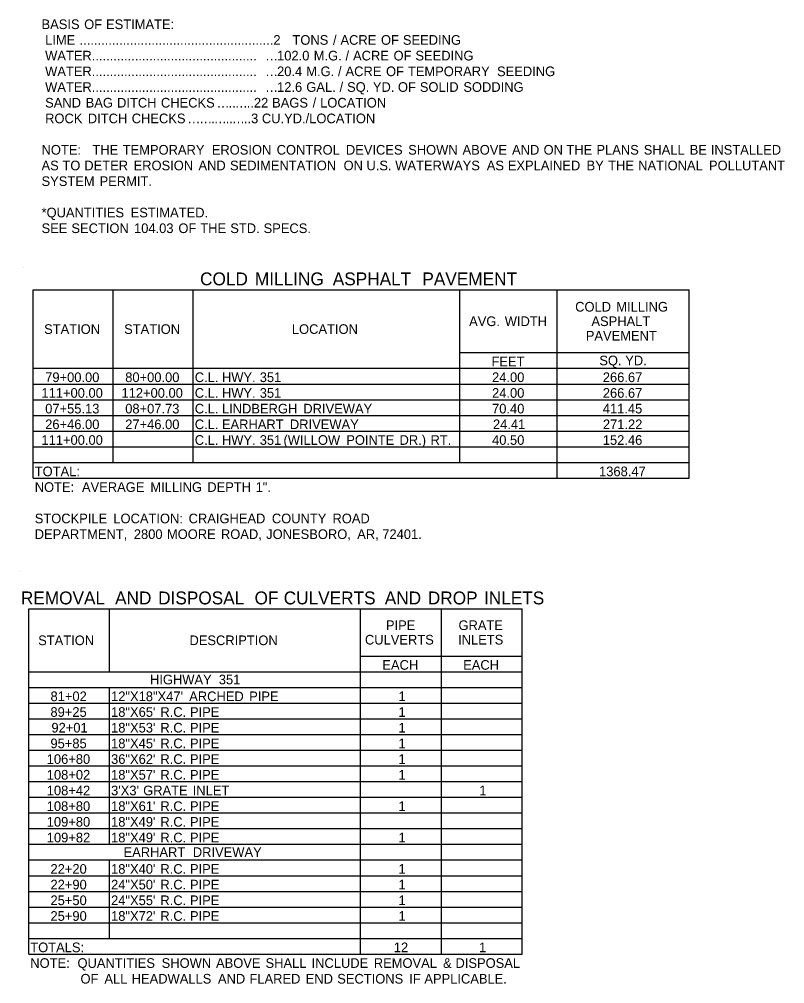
# Model space of a CAD drawing. Extents: x 1197542 to 1207068, y 230488 to 237324.
# Drawn here: x 1199831 to 1200307, y 231772 to 232371 of the extents above; entities that cross this region are included whole.
import ezdxf

# ---------------------------------------------------------------- set-up
doc = ezdxf.new("R2010")
doc.units = 0
doc.layers.add('Default', color=7, linetype='Continuous')

msp = doc.modelspace()

# ---------------------------------------------------------------- linework, layer by layer
at = {"layer": 'Default'}
for p, q in [((1199834.14, 232216.72), (1199834.14, 232216.72)), ((1199839.99, 232203.07), (1200247.54, 232203.07)), ((1199839.99, 232086.07), (1199839.99, 232203.07)), ((1199839.99, 232086.07), (1199839.99, 232203.07)), ((1199889.71, 232095.82), (1199889.71, 232203.07)), ((1199939.44, 232095.82), (1199939.44, 232203.07)), ((1200105.19, 232095.82), (1200105.19, 232203.07)), ((1200165.64, 232086.07), (1200165.64, 232203.07)), ((1200247.54, 232086.07), (1200247.54, 232203.07)), ((1200247.54, 232086.07), (1200247.54, 232203.07)), ((1200105.19, 232164.07), (1200247.54, 232164.07)), ((1200105.19, 232095.82), (1200105.19, 232164.07)), ((1199839.99, 232154.32), (1200247.54, 232154.32)), ((1199889.71, 232095.82), (1199889.71, 232154.32)), ((1199939.44, 232095.82), (1199939.44, 232154.32)), ((1200165.64, 232095.82), (1200165.64, 232154.32)), ((1199839.99, 232144.57), (1200247.54, 232144.57)), ((1199839.99, 232134.82), (1200247.54, 232134.82)), ((1199839.99, 232125.07), (1200247.54, 232125.07)), ((1199839.99, 232115.32), (1200247.54, 232115.32)), ((1199839.99, 232105.57), (1200247.54, 232105.57)), ((1199939.44, 232105.57), (1200105.19, 232105.57)), ((1200105.19, 232105.57), (1200247.54, 232105.57)), ((1199839.99, 232095.82), (1199889.71, 232095.82)), ((1199839.99, 232095.82), (1200247.54, 232095.82)), ((1199889.71, 232095.82), (1199939.44, 232095.82)), ((1199939.44, 232095.82), (1200105.19, 232095.82)), ((1200165.64, 232095.82), (1200247.54, 232095.82)), ((1199839.99, 232086.07), (1200247.54, 232086.07)), ((1199831.36, 232028.21), (1199831.36, 232028.21)), ((1199837.21, 232004.81), (1200143.85, 232004.81)), ((1199837.21, 231790.31), (1199837.21, 232004.81)), ((1199837.21, 231790.31), (1199837.21, 232004.81)), ((1199887.42, 231965.81), (1199887.42, 232004.81)), ((1200043.42, 231790.31), (1200043.42, 232004.81)), ((1200093.64, 231790.31), (1200093.64, 232004.81)), ((1200143.85, 231790.31), (1200143.85, 232004.81)), ((1200043.42, 231975.56), (1200143.85, 231975.56)), ((1200093.64, 231878.06), (1200093.64, 231975.56)), ((1199837.21, 231965.81), (1200143.85, 231965.81)), ((1200093.64, 231965.81), (1200143.85, 231965.81)), ((1199837.21, 231956.06), (1200043.42, 231956.06)), ((1199887.42, 231878.06), (1199887.42, 231956.06)), ((1199887.42, 231858.56), (1199887.42, 231956.06)), ((1200043.42, 231956.06), (1200143.85, 231956.06)), ((1200043.42, 231858.56), (1200043.42, 231956.06)), ((1199837.21, 231946.31), (1200143.85, 231946.31)), ((1199837.21, 231936.56), (1200143.85, 231936.56)), ((1199837.21, 231926.81), (1200143.85, 231926.81)), ((1199837.21, 231917.06), (1200143.85, 231917.06)), ((1199837.21, 231907.31), (1200143.85, 231907.31)), ((1199837.21, 231897.56), (1200143.85, 231897.56)), ((1199837.21, 231887.81), (1200143.85, 231887.81)), ((1199837.21, 231878.06), (1200143.85, 231878.06)), ((1199887.42, 231878.06), (1200043.42, 231878.06)), ((1200043.42, 231878.06), (1200143.85, 231878.06)), ((1199837.21, 231868.31), (1200143.85, 231868.31)), ((1199887.42, 231868.31), (1200043.42, 231868.31)), ((1200043.42, 231868.31), (1200093.64, 231868.31)), ((1200093.64, 231868.31), (1200143.85, 231868.31)), ((1199837.21, 231858.56), (1200043.42, 231858.56)), ((1199887.42, 231858.56), (1200043.42, 231858.56)), ((1200043.42, 231858.56), (1200143.85, 231858.56)), ((1200093.64, 231858.56), (1200143.85, 231858.56)), ((1200093.64, 231790.31), (1200093.64, 231858.56)), ((1199837.21, 231848.81), (1200043.42, 231848.81)), ((1199887.42, 231800.06), (1199887.42, 231848.81)), ((1199887.42, 231800.06), (1199887.42, 231848.81)), ((1200043.42, 231848.81), (1200143.85, 231848.81)), ((1200043.42, 231790.31), (1200043.42, 231848.81)), ((1199837.21, 231839.06), (1200143.85, 231839.06)), ((1199837.21, 231829.31), (1200143.85, 231829.31)), ((1199837.21, 231819.56), (1200143.85, 231819.56)), ((1199837.21, 231809.81), (1200143.85, 231809.81)), ((1199837.21, 231800.06), (1200143.85, 231800.06)), ((1199837.21, 231790.31), (1200143.85, 231790.31))]:
    msp.add_line(p, q, dxfattribs=at)

# ---------------------------------------------------------------- texts
for s, height, p in [('BASIS', 6, (1199845.19, 232365.11)), (' OF', 6, (1199869.45, 232365.11)), (' ESTIMATE:', 6, (1199883.04, 232365.11)), (' LIME', 6, (1199845.19, 232355.36)), (' ......................................................2', 6, (1199866.63, 232355.36)), (' TONS', 6, (1199998.88, 232355.36)), (' /', 6, (1200024.06, 232355.36)), (' ACRE', 6, (1200028.72, 232355.36)), (' OF', 6, (1200053.89, 232355.36)), (' SEEDING', 6, (1200067.48, 232355.36)), (' WATER..............................................', 6, (1199845.19, 232345.61)), ('102.0', 6, (1199991.54, 232345.61)), (' M.G.', 6, (1200012.1, 232345.61)), (' /', 6, (1200031.86, 232345.61)), (' ACRE', 6, (1200036.52, 232345.61)), (' OF', 6, (1200061.69, 232345.61)), (' SEEDING', 6, (1200075.28, 232345.61)), ('…', 6, (1199984.14, 232345.61)), (' WATER..............................................', 6, (1199845.19, 232335.86)), ('20.4', 6, (1199991.54, 232335.86)), (' M.G.', 6, (1200007.44, 232335.86)), (' /', 6, (1200027.19, 232335.86)), (' ACRE', 6, (1200031.85, 232335.86)), (' OF', 6, (1200057.03, 232335.86)), (' TEMPORARY', 6, (1200070.62, 232335.86)), (' SEEDING', 6, (1200125.99, 232335.86)), (' WATER..............................................', 6, (1199845.19, 232326.11)), ('…', 6, (1199984.14, 232335.86)), ('12.6', 6, (1199991.54, 232326.11)), (' GAL.', 6, (1200007.47, 232326.11)), (' /', 6, (1200028.16, 232326.11)), (' SQ.', 6, (1200032.82, 232326.11)), (' YD.', 6, (1200048.86, 232326.11)), (' OF', 6, (1200064.43, 232326.11)), (' SOLID', 6, (1200078.02, 232326.11)), (' SODDING', 6, (1200105.06, 232326.11)), ('…', 6, (1199984.14, 232326.11)), (' SAND', 6, (1199845.19, 232316.36)), (' BAG', 6, (1199870.37, 232316.36)), (' DITCH', 6, (1199889.88, 232316.36)), (' CHECKS', 6, (1199917.14, 232316.36)), ('..22', 6, (1199972.7, 232316.36)), (' BAGS', 6, (1199986.23, 232316.36)), (' /', 6, (1200011.42, 232316.36)), (' LOCATION', 6, (1200016.08, 232316.36)), ('…', 6, (1199953.97, 232316.36)), ('..', 6, (1199961.37, 232316.36)), ('…', 6, (1199965.3, 232316.36)), (' ROCK', 6, (1199845.19, 232306.61)), (' DITCH', 6, (1199871.72, 232306.61)), (' CHECKS', 6, (1199898.99, 232306.61)), ('..3', 6, (1199970.94, 232306.61)), (' CU.YD./LOCATION', 6, (1199979.88, 232306.61)), ('…', 6, (1199935.82, 232306.61)), ('…', 6, (1199943.22, 232306.61)), ('.', 6, (1199950.62, 232306.61)), ('…', 6, (1199952.22, 232306.61)), ('..', 6, (1199959.62, 232306.61)), ('…', 6, (1199963.54, 232306.61)), ('NOTE:', 6, (1199845.19, 232287.11)), ('   THE', 6, (1199870.08, 232287.11)), (' TEMPORARY', 6, (1199893.38, 232287.11)), (' EROSION', 6, (1199948.75, 232287.11)), (' CONTROL', 6, (1199989.06, 232287.11)), (' DEVICES', 6, (1200032.08, 232287.11)), (' SHOWN', 6, (1200070.78, 232287.11)), (' ABOVE', 6, (1200104.56, 232287.11)), (' AND', 6, (1200135.33, 232287.11)), (' ON', 6, (1200154.91, 232287.11)), (' THE', 6, (1200169.13, 232287.11)), (' PLANS', 6, (1200187.78, 232287.11)), (' SHALL', 6, (1200217.16, 232287.11)), (' BE', 6, (1200245.75, 232287.11)), (' INSTALLED', 6, (1200258.82, 232287.11)), ('AS', 6, (1199845.19, 232277.36)), (' TO', 6, (1199855.94, 232277.36)), (' DETER', 6, (1199869.53, 232277.36)), (' EROSION', 6, (1199900.16, 232277.36)), (' AND', 6, (1199940.47, 232277.36)), (' SEDIMENTATION', 6, (1199960.06, 232277.36)), (' ON', 6, (1200030.64, 232277.36)), (' U.S.', 6, (1200044.86, 232277.36)), (' WATERWAYS', 6, (1200062.75, 232277.36)), (' AS', 6, (1200119.61, 232277.36)), (' EXPLAINED', 6, (1200132.68, 232277.36)), (' BY', 6, (1200181.63, 232277.36)), (' THE', 6, (1200195.07, 232277.36)), (' NATIONAL', 6, (1200213.72, 232277.36)), (' POLLUTANT', 6, (1200257.68, 232277.36)), ('SYSTEM', 6, (1199845.19, 232267.61)), (' PERMIT.', 6, (1199879.04, 232267.61)), ('*QUANTITIES', 6, (1199845.19, 232248.11)), (' ESTIMATED.', 6, (1199898.32, 232248.11)), ('SEE', 6, (1199845.19, 232238.36)), (' SECTION', 6, (1199861.52, 232238.36)), (' 104.03', 6, (1199900.43, 232238.36)), (' OF', 6, (1199928.01, 232238.36)), (' THE', 6, (1199941.59, 232238.36)), (' STD.', 6, (1199960.24, 232238.36)), (' SPECS.', 6, (1199980.94, 232238.36)), ('COLD', 8, (1199943.69, 232205.89)), (' MILLING', 8, (1199974.81, 232205.89)), (' ASPHALT', 8, (1200023.18, 232205.89)), (' PAVEMENT', 8, (1200078.85, 232205.89)), ('COLD', 6, (1200176.78, 232189.57)), (' MILLING', 6, (1200200.12, 232189.57)), ('AVG.', 6, (1200110.88, 232180.57)), (' WIDTH', 6, (1200130.8, 232180.57)), ('ASPHALT', 6, (1200186.88, 232180.57)), ('STATION', 6, (1199846.79, 232175.69)), ('STATION', 6, (1199896.51, 232175.69)), ('LOCATION', 6, (1200000.76, 232175.69)), ('PAVEMENT', 6, (1200183.38, 232171.57)), ('FEET', 6, (1200124.79, 232155.52)), ('SQ.', 6, (1200191.79, 232156.19)), (' YD.', 6, (1200205.66, 232156.19)), ('79+00.00', 6, (1199847.46, 232145.77)), ('80+00.00', 6, (1199897.19, 232145.77)), ('C.L.', 6, (1199940.41, 232145.77)), (' HWY.', 6, (1199955.05, 232145.77)), (' 351', 6, (1199978.54, 232145.77)), ('24.00', 6, (1200125.13, 232145.77)), ('266.67', 6, (1200193.96, 232145.77)), ('111+00.00', 6, (1199845.13, 232136.02)), ('112+00.00', 6, (1199894.86, 232136.02)), ('C.L.', 6, (1199940.41, 232136.02)), (' HWY.', 6, (1199955.05, 232136.02)), (' 351', 6, (1199978.54, 232136.02)), ('24.00', 6, (1200125.13, 232136.02)), ('266.67', 6, (1200193.96, 232136.02)), ('07+55.13', 6, (1199847.45, 232126.27)), ('08+07.73', 6, (1199897.18, 232126.27)), ('C.L.', 6, (1199940.41, 232126.27)), (' LINDBERGH', 6, (1199955.05, 232126.27)), (' DRIVEWAY', 6, (1200005.62, 232126.27)), ('70.40', 6, (1200125.13, 232126.27)), ('411.45', 6, (1200193.94, 232126.27)), ('26+46.00', 6, (1199847.46, 232116.52)), ('27+46.00', 6, (1199897.19, 232116.52)), ('C.L.', 6, (1199940.41, 232116.52)), (' EARHART', 6, (1199955.05, 232116.52)), (' DRIVEWAY', 6, (1199997.28, 232116.52)), ('24.41', 6, (1200125.7, 232116.52)), ('271.22', 6, (1200194, 232116.52)), ('111+00.00', 6, (1199845.13, 232106.77)), ('C.L.', 6, (1199940.41, 232106.77)), (' HWY.', 6, (1199955.05, 232106.77)), (' 351', 6, (1199978.54, 232106.77)), (' (WILLOW', 6, (1199993.3, 232106.77)), (' POINTE', 6, (1200032.32, 232106.77)), (' DR.)', 6, (1200065.41, 232106.77)), (' RT.', 6, (1200084.66, 232106.77)), ('40.50', 6, (1200125.13, 232106.77)), ('152.46', 6, (1200193.96, 232106.77)), ('TOTAL:', 6, (1199840.96, 232087.27)), ('1368.47', 6, (1200191.63, 232087.27)), ('NOTE:', 6, (1199840.96, 232077.52)), ('  AVERAGE', 6, (1199865.85, 232077.52)), (' MILLING', 6, (1199910.6, 232077.52)), (' DEPTH', 6, (1199945.94, 232077.52)), (' 1".', 6, (1199976, 232077.52)), ('STOCKPILE', 6, (1199840.96, 232058.02)), (' LOCATION:', 6, (1199887.57, 232058.02)), (' CRAIGHEAD', 6, (1199934.35, 232058.02)), (' COUNTY', 6, (1199986.08, 232058.02)), (' ROAD', 6, (1200023.74, 232058.02)), ('DEPARTMENT,', 6, (1199840.96, 232048.27)), (' 2800', 6, (1199900.31, 232048.27)), (' MOORE', 6, (1199920.88, 232048.27)), (' ROAD,', 6, (1199954.43, 232048.27)), (' JONESBORO,', 6, (1199982.56, 232048.27)), (' AR,', 6, (1200039.12, 232048.27)), (' 72401.', 6, (1200054.68, 232048.27)), ('REMOVAL', 8, (1199832.34, 232007.64)), (' AND', 8, (1199887.9, 232007.64)), (' DISPOSAL', 8, (1199914.67, 232007.64)), (' OF', 8, (1199974.58, 232007.64)), (' CULVERTS', 8, (1199992.69, 232007.64)), (' AND', 8, (1200055.5, 232007.64)), (' DROP', 8, (1200082.26, 232007.64)), (' INLETS', 8, (1200117.15, 232007.64)), ('PIPE', 6, (1200059.19, 231991.69)), ('GRATE', 6, (1200104.28, 231991.69)), ('STATION', 6, (1199843.09, 231982.31)), ('DESCRIPTION', 6, (1199937.11, 231982.31)), ('CULVERTS', 6, (1200046.14, 231982.69)), ('INLETS', 6, (1200104.04, 231982.69)), ('EACH', 6, (1200056.97, 231967.01)), ('EACH', 6, (1200107.19, 231967.01)), ('HIGHWAY', 6, (1199912.58, 231957.94)), (' 351', 6, (1199953.11, 231957.94)), ('81+02', 6, (1199850.77, 231947.51)), ('12"X18"X47\'', 6, (1199888.4, 231947.51)), (' ARCHED', 6, (1199934.71, 231947.51)), (' PIPE', 6, (1199971.99, 231947.51)), ('1', 6, (1200066.97, 231947.51)), ('89+25', 6, (1199850.72, 231937.76)), ('18"X65\'', 6, (1199888.4, 231937.76)), (' R.C.', 6, (1199916.82, 231937.76)), (' PIPE', 6, (1199935.18, 231937.76)), ('1', 6, (1200066.97, 231937.76)), ('92+01', 6, (1199851.32, 231928.01)), ('18"X53\'', 6, (1199888.4, 231928.01)), (' R.C.', 6, (1199916.82, 231928.01)), (' PIPE', 6, (1199935.18, 231928.01)), ('1', 6, (1200066.97, 231928.01)), ('95+85', 6, (1199850.72, 231918.26)), ('18"X45\'', 6, (1199888.4, 231918.26)), (' R.C.', 6, (1199916.82, 231918.26)), (' PIPE', 6, (1199935.18, 231918.26)), ('1', 6, (1200066.97, 231918.26)), ('106+80', 6, (1199848.42, 231908.51)), ('36"X62\'', 6, (1199888.4, 231908.51)), (' R.C.', 6, (1199916.82, 231908.51)), (' PIPE', 6, (1199935.18, 231908.51)), ('1', 6, (1200066.97, 231908.51)), ('108+02', 6, (1199848.44, 231898.76)), ('18"X57\'', 6, (1199888.4, 231898.76)), (' R.C.', 6, (1199916.82, 231898.76)), (' PIPE', 6, (1199935.18, 231898.76)), ('1', 6, (1200066.97, 231898.76)), ('108+42', 6, (1199848.44, 231889.01)), ("3'X3'", 6, (1199888.4, 231889.01)), (' GRATE', 6, (1199906.12, 231889.01)), (' INLET', 6, (1199936.88, 231889.01)), ('1', 6, (1200117.18, 231889.01)), ('108+80', 6, (1199848.42, 231879.26)), ('18"X61\'', 6, (1199888.4, 231879.26)), (' R.C.', 6, (1199916.82, 231879.26)), (' PIPE', 6, (1199935.18, 231879.26)), ('1', 6, (1200066.97, 231879.26)), ('109+80', 6, (1199848.42, 231869.51)), ('18"X49\'', 6, (1199888.4, 231869.51)), (' R.C.', 6, (1199916.82, 231869.51)), (' PIPE', 6, (1199935.18, 231869.51)), ('109+82', 6, (1199848.44, 231859.76)), ('18"X49\'', 6, (1199888.4, 231859.76)), (' R.C.', 6, (1199916.82, 231859.76)), (' PIPE', 6, (1199935.18, 231859.76)), ('1', 6, (1200066.97, 231859.76)), ('EARHART', 6, (1199896.15, 231850.69)), (' DRIVEWAY', 6, (1199936.96, 231850.69)), ('22+20', 6, (1199850.75, 231840.26)), ('18"X40\'', 6, (1199888.4, 231840.26)), (' R.C.', 6, (1199916.82, 231840.26)), (' PIPE', 6, (1199935.18, 231840.26)), ('1', 6, (1200066.97, 231840.26)), ('22+90', 6, (1199850.75, 231830.51)), ('24"X50\'', 6, (1199888.4, 231830.51)), (' R.C.', 6, (1199916.82, 231830.51)), (' PIPE', 6, (1199935.18, 231830.51)), ('1', 6, (1200066.97, 231830.51)), ('25+50', 6, (1199850.75, 231820.76)), ('24"X55\'', 6, (1199888.4, 231820.76)), (' R.C.', 6, (1199916.82, 231820.76)), (' PIPE', 6, (1199935.18, 231820.76)), ('1', 6, (1200066.97, 231820.76)), ('25+90', 6, (1199850.75, 231811.01)), ('18"X72\'', 6, (1199888.4, 231811.01)), (' R.C.', 6, (1199916.82, 231811.01)), (' PIPE', 6, (1199935.18, 231811.01)), ('1', 6, (1200066.97, 231811.01)), ('TOTALS:', 6, (1199838.19, 231791.51)), ('12', 6, (1200064.08, 231791.51)), ('1', 6, (1200117.09, 231791.51)), ('NOTE:', 6, (1199838.19, 231781.76)), ('  QUANTITIES', 6, (1199863.07, 231781.76)), (' SHOWN', 6, (1199917.6, 231781.76)), (' ABOVE', 6, (1199951.38, 231781.76)), (' SHALL', 6, (1199982.15, 231781.76)), (' INCLUDE', 6, (1200010.74, 231781.76)), (' REMOVAL', 6, (1200049.42, 231781.76)), (' &', 6, (1200092.45, 231781.76)), (' DISPOSAL', 6, (1200100.18, 231781.76)), ('              OF', 6, (1199838.19, 231772.01)), (' ALL', 6, (1199882.03, 231772.01)), (' HEADWALLS', 6, (1199898.98, 231772.01)), (' AND', 6, (1199952.58, 231772.01)), (' FLARED', 6, (1199972.16, 231772.01)), (' END', 6, (1200007.12, 231772.01)), (' SECTIONS', 6, (1200026.7, 231772.01)), (' IF', 6, (1200071.45, 231772.01)), (' APPLICABLE.', 6, (1200080.84, 231772.01))]:
    msp.add_text(s, height=height, dxfattribs=at).set_placement(p)

doc.saveas('drawing.dxf')
